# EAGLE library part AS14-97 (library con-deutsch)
DEUTSCH Connector
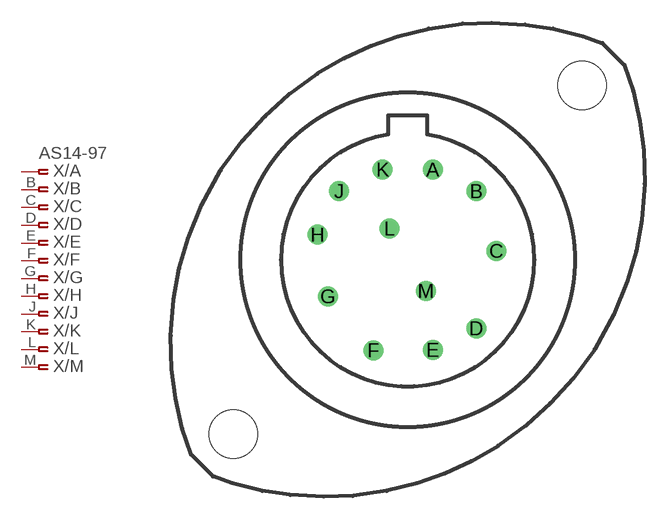
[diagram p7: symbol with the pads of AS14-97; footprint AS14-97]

Designator prefix X; gates /A=PINF_VAL /B=ASPINF /C=ASPINF /D=ASPINF /E=ASPINF /F=ASPINF /G=ASPINF /H=ASPINF /J=ASPINF /K=ASPINF /L=ASPINF /M=ASPINF

## AS14-97 (OC_FARNELL: unknown; OC_NEWARK: unknown)  [AS14-97]
A  /A:1  pas
B  /B:1  pas
C  /C:1  pas
D  /D:1  pas
E  /E:1  pas
F  /F:1  pas
G  /G:1  pas
H  /H:1  pas
J  /J:1  pas
K  /K:1  pas
L  /L:1  pas
M  /M:1  pas

## Footprint AS14-97 (pad centres in mm)
DEUTSCH Connector
drill 0.813 round: A 1.651,5.944; B 4.521,4.521; C 5.842,0.584; D 4.521,-4.521; E 1.651,-5.944; F -2.261,-5.969; G -5.258,-2.413; H -5.944,1.651; J -4.521,4.521; K -1.651,5.944; L -1.194,2.057; M 1.194,-2.057
hole 3.2 at 11.493,11.493
hole 3.2 at -11.493,-11.493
